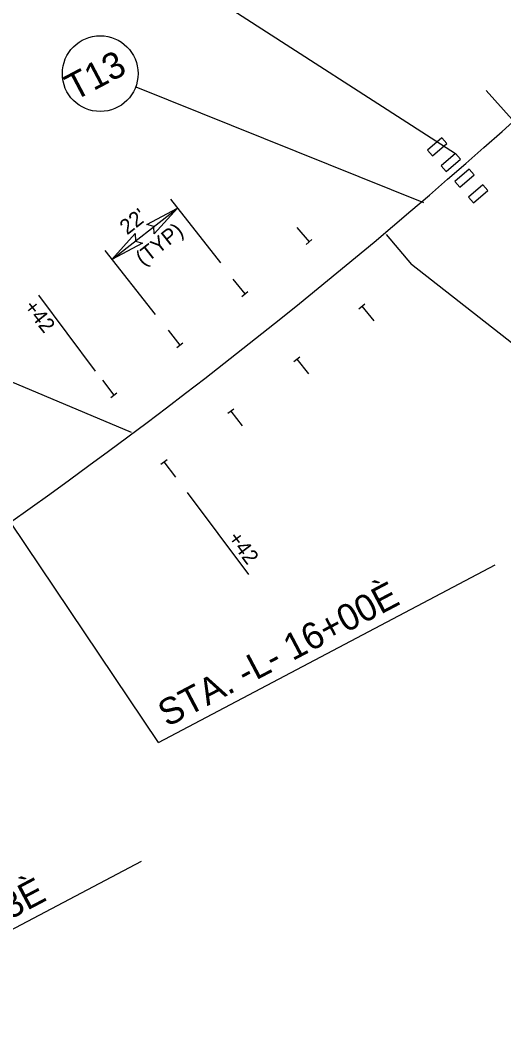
# Model space of a CAD drawing. Extents: x 1487421 to 1489048, y 497792 to 499463.
# Drawn here: x 1488279 to 1488406.6, y 498498.9 to 498767.8 of the extents above; entities that cross this region are included whole.
import ezdxf

# ---------------------------------------------------------------- set-up
doc = ezdxf.new("R2010")
doc.units = 0
for name, color, linetype in [('Prop Dimension', 7, 'Continuous'), ('Prop Dimension Text', 7, 'Continuous'), ('Prop Mkg Solid Dbl Yel Rpm 80ft', 7, 'Continuous'), ('Prop Mkg Solid White Lane Line', 7, 'Continuous'), ('Scratch_Level_3', 7, 'Continuous'), ('Scratch_Level_6', 7, 'Continuous'), ('Text', 7, 'Continuous')]:
    doc.layers.add(name, color=color, linetype=linetype)

msp = doc.modelspace()

# ---------------------------------------------------------------- linework, layer by layer
at = {"layer": 'Prop Dimension'}
for p, q in [((1488303.17, 498704.69), (1488320.46, 498718.28)), ((1488318.61, 498720.64), (1488331.87, 498703.77)), ((1488301.31, 498707.05), (1488314.58, 498690.17)), ((1488298.86, 498675.18), (1488283.86, 498695.29)), ((1488323.01, 498643.13), (1488339.25, 498621.48))]:
    msp.add_line(p, q, dxfattribs=at)
for points in [[(1488312.43, 498713.94), (1488320.46, 498718.28), (1488314.34, 498711.43), (1488314.25, 498713.4)], [(1488311.2, 498709.03), (1488303.17, 498704.69), (1488309.29, 498711.54), (1488309.38, 498709.57)]]:
    msp.add_lwpolyline(points, close=True, dxfattribs=at)
at = {"layer": 'Prop Mkg Solid Dbl Yel Rpm 80ft'}
msp.add_arc((1487424.96, 499839.79), 1475, 305.25533, 321.11565, dxfattribs=at)
at = {"layer": 'Prop Mkg Solid White Lane Line'}
for p, q in [((1488352.03, 498713.18), (1488355.21, 498709.32)), ((1488354.44, 498708.69), (1488355.98, 498709.96)), ((1488335.12, 498699.48), (1488338.24, 498695.58)), ((1488337.46, 498694.95), (1488339.03, 498696.2)), ((1488368.41, 498691.7), (1488369.96, 498692.97)), ((1488369.19, 498692.34), (1488372.36, 498688.48)), ((1488318.02, 498686.04), (1488321.08, 498682.08)), ((1488320.28, 498681.48), (1488321.88, 498682.68)), ((1488351.19, 498677.76), (1488352.75, 498679)), ((1488351.97, 498678.38), (1488355.09, 498674.47)), ((1488300.71, 498672.84), (1488303.71, 498668.84)), ((1488302.91, 498668.24), (1488304.51, 498669.45)), ((1488333.74, 498664.08), (1488335.34, 498665.28)), ((1488334.54, 498664.68), (1488337.6, 498660.73)), ((1488316.12, 498650.65), (1488317.72, 498651.85)), ((1488316.92, 498651.25), (1488319.92, 498647.25))]:
    msp.add_line(p, q, dxfattribs=at)
at = {"layer": 'Scratch_Level_3'}
for p, q in [((1488322.17, 498778.92), (1488393.88, 498732.71)), ((1488408.87, 498741.63), (1488402.01, 498749.28)), ((1488390.26, 498736.86), (1488386.5, 498733.57)), ((1488387.81, 498732.06), (1488391.58, 498735.35)), ((1488391.58, 498735.35), (1488390.26, 498736.86)), ((1488386.5, 498733.57), (1488387.81, 498732.06)), ((1488393.88, 498732.71), (1488390.11, 498729.43)), ((1488395.19, 498731.2), (1488393.88, 498732.71)), ((1488390.11, 498729.43), (1488391.43, 498727.92)), ((1488391.43, 498727.92), (1488395.19, 498731.2)), ((1488397.49, 498728.57), (1488393.73, 498725.28)), ((1488395.04, 498723.77), (1488398.81, 498727.06)), ((1488398.81, 498727.06), (1488397.49, 498728.57)), ((1488393.73, 498725.28), (1488395.04, 498723.77)), ((1488401.11, 498724.42), (1488397.34, 498721.14)), ((1488402.42, 498722.91), (1488401.11, 498724.42)), ((1488397.34, 498721.14), (1488398.66, 498719.63)), ((1488398.66, 498719.63), (1488402.42, 498722.91)), ((1488375.58, 498711.33), (1488382.25, 498703.41)), ((1488449.84, 498650.34), (1488382.25, 498703.41))]:
    msp.add_line(p, q, dxfattribs=at)
at = {"layer": 'Scratch_Level_6'}
msp.add_line((1488222.16, 498498.93), (1488311, 498545.83), dxfattribs=at)
at = {"layer": 'Text'}
for p, q in [((1488309.45, 498750.28), (1488385.45, 498719.71)), ((1488219.07, 498696.58), (1488308.29, 498659.12)), ((1488315.5, 498577.12), (1488276.37, 498635.32)), ((1488315.5, 498577.12), (1488404.33, 498624.02))]:
    msp.add_line(p, q, dxfattribs=at)
msp.add_circle((1488300.08, 498753.78), 10, dxfattribs=at)

# ---------------------------------------------------------------- texts
at = {"layer": 'Prop Dimension'}
for s, p in [("22'", (1488307.2, 498711.04)), ('(TYP)', (1488311.4, 498702.89))]:
    msp.add_text(s, height=4, rotation=38.1877, dxfattribs=at).set_placement(p)
at = {"layer": 'Prop Dimension Text'}
for rotation, p in [(308.4938, (1488279.7, 498692.06)), (306.8868, (1488333.57, 498631.04))]:
    msp.add_text('+42', height=4, rotation=rotation, dxfattribs=at).set_placement(p)
at = {"layer": 'Scratch_Level_6'}
msp.add_text('STA. -L- 14+83È', height=7, rotation=27.835, dxfattribs=at).set_placement((1488224.41, 498502.92))
at = {"layer": 'Text'}
for s, p in [('T13', (1488293.24, 498746.48)), ('STA. -L- 16+00È', (1488317.75, 498581.11))]:
    msp.add_text(s, height=7, rotation=27.835, dxfattribs=at).set_placement(p)

doc.saveas('drawing.dxf')
